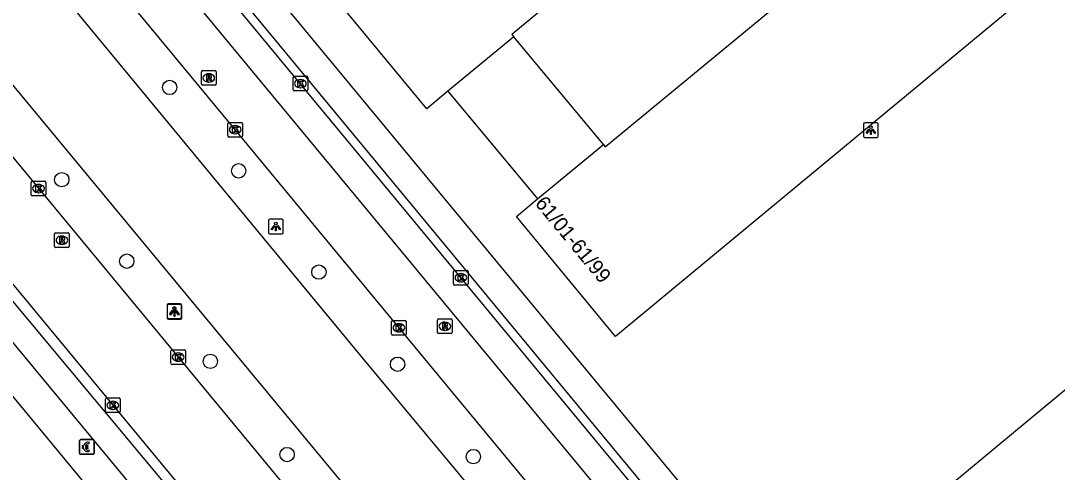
# Model space of a CAD drawing. Extents: x 159489 to 160304, y 383826 to 384530.
# Drawn here: x 159992.1 to 160062.8, y 384204.7 to 384235.5 of the extents above; entities that cross this region are included whole.
import ezdxf

# ---------------------------------------------------------------- set-up
doc = ezdxf.new("R2010")
doc.units = 0
for name, color, linetype in [('IMGEO_Betaalautomaat', 7, 'Continuous'), ('IMGEO_Boom', 7, 'Continuous'), ('IMGEO_Fietspad_gesloten', 7, 'Continuous'), ('IMGEO_Kolk', 7, 'Continuous'), ('IMGEO_Lichtpunt', 7, 'Continuous'), ('IMGEO_OVBaan_gesloten', 7, 'Continuous'), ('IMGEO_Pand', 7, 'Continuous'), ('IMGEO_Pand_nummerreeks', 7, 'Continuous'), ('IMGEO_Pand_overbouw', 7, 'Continuous'), ('IMGEO_Rijbaan_lokaal_gesloten', 7, 'Continuous'), ('IMGEO_Rioolput', 7, 'Continuous'), ('IMGEO_Voetpad_open', 7, 'Continuous')]:
    doc.layers.add(name, color=color, linetype=linetype)

msp = doc.modelspace()

# ---------------------------------------------------------------- linework, layer by layer
at = {"layer": 'IMGEO_Betaalautomaat'}
for p, q in [((159996.11, 384206.021), (159996.11, 384206.862)), ((159996.11, 384206.862), (159996.11, 384206.021)), ((159996.185, 384206.945), (159997.026, 384206.945)), ((159997.026, 384206.945), (159996.185, 384206.945)), ((159996.772, 384206.75), (159996.755, 384206.65)), ((159997.109, 384206.871), (159997.109, 384206.03)), ((159997.109, 384206.03), (159997.109, 384206.871)), ((159996.393, 384206.409), (159996.393, 384206.477)), ((159996.514, 384206.477), (159996.514, 384206.409)), ((159996.759, 384206.244), (159996.781, 384206.157)), ((159997.035, 384205.946), (159996.194, 384205.946)), ((159996.194, 384205.946), (159997.035, 384205.946))]:
    msp.add_line(p, q, dxfattribs=at)
for points in [[(159996.393, 384206.477), (159996.324, 384206.477), (159996.324, 384206.546), (159996.403, 384206.546)], [(159996.398, 384206.34), (159996.324, 384206.34), (159996.324, 384206.409), (159996.393, 384206.409)], [(159996.525, 384206.546), (159996.672, 384206.546), (159996.672, 384206.477), (159996.514, 384206.477)], [(159996.514, 384206.409), (159996.672, 384206.409), (159996.672, 384206.34), (159996.528, 384206.34)]]:
    msp.add_lwpolyline(points, dxfattribs=at)
for centre, radius, start, end in [((159996.188, 384206.868), 0.0779, 92.4484, 184.28452), ((159996.188, 384206.868), 0.0779, 92.4484, 184.28452), ((159996.686, 384206.47), 0.293, 73.01398, 165.01395), ((159997.032, 384206.868), 0.0779, 2.4484, 94.28452), ((159997.032, 384206.868), 0.0779, 2.4484, 94.28452), ((159996.188, 384206.024), 0.0779, 182.4484, 274.28452), ((159996.188, 384206.024), 0.0779, 182.4484, 274.28452), ((159996.659, 384206.395), 0.267, 191.80956, 297.03891), ((159996.692, 384206.483), 0.179, 69.32359, 159.56827), ((159996.692, 384206.41), 0.179, 202.76249, 291.86925), ((159997.032, 384206.024), 0.0779, 272.4484, 4.28452), ((159997.032, 384206.024), 0.0779, 272.4484, 4.28452)]:
    msp.add_arc(centre, radius, start, end, dxfattribs=at)
at = {"layer": 'IMGEO_Boom'}
for centre in [(160002.259, 384230.941), (159994.902, 384224.654), (160006.962, 384225.258), (159999.338, 384219.104), (160012.433, 384218.36), (160005.035, 384212.279), (160017.798, 384212.08), (160010.267, 384205.93), (160022.961, 384205.789)]:
    msp.add_circle(centre, 0.489, dxfattribs=at)
at = {"layer": 'IMGEO_Fietspad_gesloten'}
for points in [[(159957.532, 384254.825), (159960.033, 384251.817), (159960.897, 384250.561), (160029.527, 384167.731), (160030.452, 384166.645)], [(159959.452, 384254.838), (159959.937, 384254.261), (159961.686, 384252.179), (160032.453, 384167.34)]]:
    msp.add_lwpolyline(points, dxfattribs=at)
at = {"layer": 'IMGEO_Kolk'}
for p, q in [((160010.674, 384230.772), (160010.674, 384231.624)), ((160010.749, 384231.698), (160011.601, 384231.698)), ((160011.162, 384231.478), (160011.187, 384231.478)), ((160011.675, 384231.624), (160011.675, 384230.772)), ((160011.185, 384230.918), (160011.16, 384230.918)), ((160011.601, 384230.698), (160010.749, 384230.698)), ((160006.229, 384227.635), (160006.229, 384228.487)), ((160006.304, 384228.561), (160007.156, 384228.561)), ((160006.717, 384228.341), (160006.742, 384228.341)), ((160007.23, 384228.487), (160007.23, 384227.635)), ((160007.156, 384227.561), (160006.304, 384227.561)), ((160006.74, 384227.781), (160006.715, 384227.781)), ((159992.819, 384223.621), (159992.819, 384224.473)), ((159992.894, 384224.547), (159993.746, 384224.547)), ((159993.82, 384224.473), (159993.82, 384223.621)), ((159993.33, 384223.767), (159993.305, 384223.767)), ((159993.307, 384224.327), (159993.332, 384224.327)), ((159993.746, 384223.547), (159992.894, 384223.547)), ((160021.615, 384217.549), (160021.615, 384218.401)), ((160021.69, 384218.475), (160022.542, 384218.475)), ((160022.103, 384218.255), (160022.128, 384218.255)), ((160022.616, 384218.401), (160022.616, 384217.549)), ((160022.542, 384217.475), (160021.69, 384217.475)), ((160022.126, 384217.695), (160022.101, 384217.695)), ((160017.388, 384214.139), (160017.388, 384214.991)), ((160017.463, 384215.065), (160018.315, 384215.065)), ((160017.876, 384214.845), (160017.901, 384214.845)), ((160018.389, 384214.991), (160018.389, 384214.139)), ((160018.315, 384214.065), (160017.463, 384214.065)), ((160017.899, 384214.285), (160017.874, 384214.285)), ((160002.412, 384213.069), (160003.264, 384213.069)), ((160002.337, 384212.143), (160002.337, 384212.995)), ((160002.825, 384212.849), (160002.85, 384212.849)), ((160003.338, 384212.995), (160003.338, 384212.143)), ((160003.264, 384212.069), (160002.412, 384212.069)), ((160002.848, 384212.289), (160002.823, 384212.289)), ((159997.884, 384208.857), (159997.884, 384209.709)), ((159997.959, 384209.783), (159998.811, 384209.783)), ((159998.372, 384209.563), (159998.397, 384209.563)), ((159998.885, 384209.709), (159998.885, 384208.857)), ((159998.395, 384209.003), (159998.37, 384209.003)), ((159998.811, 384208.783), (159997.959, 384208.783))]:
    msp.add_line(p, q, dxfattribs=at)
for points in [[(160010.674, 384230.772), (160010.674, 384231.624)], [(160010.749, 384231.698), (160011.601, 384231.698)], [(160011.675, 384231.624), (160011.675, 384230.772)], [(160010.995, 384231.398), (160011.118, 384231.398), (160011.118, 384231.247), (160011.248, 384231.398), (160011.412, 384231.398), (160011.266, 384231.247), (160011.419, 384230.998), (160011.267, 384230.998), (160011.182, 384231.162), (160011.118, 384231.095), (160011.118, 384230.998), (160010.995, 384230.998), (160010.995, 384231.398)], [(160011.601, 384230.698), (160010.749, 384230.698)], [(160006.229, 384227.635), (160006.229, 384228.487)], [(160006.304, 384228.561), (160007.156, 384228.561)], [(160006.55, 384228.261), (160006.673, 384228.261), (160006.673, 384228.11), (160006.803, 384228.261), (160006.967, 384228.261), (160006.821, 384228.11), (160006.974, 384227.861), (160006.822, 384227.861), (160006.737, 384228.025), (160006.673, 384227.958), (160006.673, 384227.861), (160006.55, 384227.861), (160006.55, 384228.261)], [(160007.23, 384228.487), (160007.23, 384227.635)], [(160007.156, 384227.561), (160006.304, 384227.561)], [(159992.819, 384223.621), (159992.819, 384224.473)], [(159992.894, 384224.547), (159993.746, 384224.547)], [(159993.82, 384224.473), (159993.82, 384223.621)], [(159993.14, 384224.247), (159993.263, 384224.247), (159993.263, 384224.096), (159993.393, 384224.247), (159993.557, 384224.247), (159993.411, 384224.096), (159993.564, 384223.847), (159993.412, 384223.847), (159993.327, 384224.011), (159993.263, 384223.944), (159993.263, 384223.847), (159993.14, 384223.847), (159993.14, 384224.247)], [(159993.746, 384223.547), (159992.894, 384223.547)], [(160021.615, 384217.549), (160021.615, 384218.401)], [(160021.69, 384218.475), (160022.542, 384218.475)], [(160021.936, 384218.175), (160022.059, 384218.175), (160022.059, 384218.024), (160022.189, 384218.175), (160022.353, 384218.175), (160022.207, 384218.024), (160022.36, 384217.775), (160022.208, 384217.775), (160022.123, 384217.939), (160022.059, 384217.872), (160022.059, 384217.775), (160021.936, 384217.775), (160021.936, 384218.175)], [(160022.616, 384218.401), (160022.616, 384217.549)], [(160022.542, 384217.475), (160021.69, 384217.475)], [(160017.388, 384214.139), (160017.388, 384214.991)], [(160017.463, 384215.065), (160018.315, 384215.065)], [(160017.709, 384214.765), (160017.832, 384214.765), (160017.832, 384214.614), (160017.962, 384214.765), (160018.126, 384214.765), (160017.98, 384214.614), (160018.133, 384214.365), (160017.981, 384214.365), (160017.896, 384214.529), (160017.832, 384214.462), (160017.832, 384214.365), (160017.709, 384214.365), (160017.709, 384214.765)], [(160018.389, 384214.991), (160018.389, 384214.139)], [(160018.315, 384214.065), (160017.463, 384214.065)], [(160002.412, 384213.069), (160003.264, 384213.069)], [(160002.337, 384212.143), (160002.337, 384212.995)], [(160002.658, 384212.769), (160002.781, 384212.769), (160002.781, 384212.618), (160002.911, 384212.769), (160003.075, 384212.769), (160002.929, 384212.618), (160003.082, 384212.369), (160002.93, 384212.369), (160002.845, 384212.533), (160002.781, 384212.466), (160002.781, 384212.369), (160002.658, 384212.369), (160002.658, 384212.769)], [(160003.338, 384212.995), (160003.338, 384212.143)], [(160003.264, 384212.069), (160002.412, 384212.069)], [(159997.884, 384208.857), (159997.884, 384209.709)], [(159997.959, 384209.783), (159998.811, 384209.783)], [(159998.885, 384209.709), (159998.885, 384208.857)], [(159998.205, 384209.483), (159998.328, 384209.483), (159998.328, 384209.332), (159998.458, 384209.483), (159998.622, 384209.483), (159998.476, 384209.332), (159998.629, 384209.083), (159998.477, 384209.083), (159998.392, 384209.247), (159998.328, 384209.18), (159998.328, 384209.083), (159998.205, 384209.083), (159998.205, 384209.483)], [(159998.811, 384208.783), (159997.959, 384208.783)]]:
    msp.add_lwpolyline(points, dxfattribs=at)
for centre, start, end in [((160010.751, 384231.622), 91.55205, 178.44795), ((160010.751, 384231.622), 91.55205, 178.44795), ((160011.599, 384231.622), 1.55205, 88.44795), ((160011.599, 384231.622), 1.55205, 88.44795), ((160010.751, 384230.774), 181.55205, 268.44795), ((160010.751, 384230.774), 181.55205, 268.44795), ((160011.599, 384230.774), 271.55205, 358.44795), ((160011.599, 384230.774), 271.55205, 358.44795), ((160006.306, 384228.485), 91.55205, 178.44795), ((160006.306, 384228.485), 91.55205, 178.44795), ((160007.154, 384228.485), 1.55205, 88.44795), ((160007.154, 384228.485), 1.55205, 88.44795), ((160006.306, 384227.637), 181.55205, 268.44795), ((160006.306, 384227.637), 181.55205, 268.44795), ((160007.154, 384227.637), 271.55205, 358.44795), ((160007.154, 384227.637), 271.55205, 358.44795), ((159992.896, 384224.471), 91.55205, 178.44795), ((159992.896, 384224.471), 91.55205, 178.44795), ((159993.744, 384224.471), 1.55205, 88.44795), ((159993.744, 384224.471), 1.55205, 88.44795), ((159992.896, 384223.623), 181.55205, 268.44795), ((159992.896, 384223.623), 181.55205, 268.44795), ((159993.744, 384223.623), 271.55205, 358.44795), ((159993.744, 384223.623), 271.55205, 358.44795), ((160021.692, 384218.399), 91.55205, 178.44795), ((160021.692, 384218.399), 91.55205, 178.44795), ((160022.54, 384218.399), 1.55205, 88.44795), ((160022.54, 384218.399), 1.55205, 88.44795), ((160021.692, 384217.551), 181.55205, 268.44795), ((160021.692, 384217.551), 181.55205, 268.44795), ((160022.54, 384217.551), 271.55205, 358.44795), ((160022.54, 384217.551), 271.55205, 358.44795), ((160017.465, 384214.989), 91.55205, 178.44795), ((160017.465, 384214.989), 91.55205, 178.44795), ((160018.313, 384214.989), 1.55205, 88.44795), ((160018.313, 384214.989), 1.55205, 88.44795), ((160017.465, 384214.141), 181.55205, 268.44795), ((160017.465, 384214.141), 181.55205, 268.44795), ((160018.313, 384214.141), 271.55205, 358.44795), ((160018.313, 384214.141), 271.55205, 358.44795), ((160002.414, 384212.993), 91.55205, 178.44795), ((160002.414, 384212.993), 91.55205, 178.44795), ((160003.262, 384212.993), 1.55205, 88.44795), ((160003.262, 384212.993), 1.55205, 88.44795), ((160002.414, 384212.145), 181.55205, 268.44795), ((160002.414, 384212.145), 181.55205, 268.44795), ((160003.262, 384212.145), 271.55205, 358.44795), ((160003.262, 384212.145), 271.55205, 358.44795), ((159997.961, 384209.707), 91.55205, 178.44795), ((159997.961, 384209.707), 91.55205, 178.44795), ((159998.809, 384209.707), 1.55205, 88.44795), ((159998.809, 384209.707), 1.55205, 88.44795), ((159997.961, 384208.859), 181.55205, 268.44795), ((159997.961, 384208.859), 181.55205, 268.44795), ((159998.809, 384208.859), 271.55205, 358.44795), ((159998.809, 384208.859), 271.55205, 358.44795)]:
    msp.add_arc(centre, 0.0765, start, end, dxfattribs=at)
for centre, major_axis, ratio, start_param, end_param in [((160011.161, 384231.198), (-0.387, 0.002), 0.722429, 4.712389, 7.853982), ((160011.186, 384231.198), (-0.39, 0.002), 0.717154, 1.570796, 4.712389), ((160006.716, 384228.061), (-0.387, 0.002), 0.722429, 4.712389, 7.853982), ((160006.741, 384228.061), (-0.39, 0.002), 0.717154, 1.570796, 4.712389), ((159993.306, 384224.047), (-0.387, 0.002), 0.722429, 4.712389, 7.853982), ((159993.331, 384224.047), (-0.39, 0.002), 0.717154, 1.570796, 4.712389), ((160022.102, 384217.975), (-0.387, 0.002), 0.722429, 4.712389, 7.853982), ((160022.127, 384217.975), (-0.39, 0.002), 0.717154, 1.570796, 4.712389), ((160017.875, 384214.565), (-0.387, 0.002), 0.722429, 4.712389, 7.853982), ((160017.9, 384214.565), (-0.39, 0.002), 0.717154, 1.570796, 4.712389), ((160002.824, 384212.569), (-0.387, 0.002), 0.722429, 4.712389, 7.853982), ((160002.849, 384212.569), (-0.39, 0.002), 0.717154, 1.570796, 4.712389), ((159998.371, 384209.283), (-0.387, 0.002), 0.722429, 4.712389, 7.853982), ((159998.396, 384209.283), (-0.39, 0.002), 0.717154, 1.570796, 4.712389)]:
    msp.add_ellipse(centre, major_axis=major_axis, ratio=ratio, start_param=start_param, end_param=end_param, dxfattribs=at)
at = {"layer": 'IMGEO_Lichtpunt'}
for p, q in [((160049.567, 384228.437), (160049.567, 384227.63)), ((160049.567, 384228.437), (160049.567, 384227.63)), ((160050.469, 384228.532), (160049.661, 384228.532)), ((160050.469, 384228.532), (160049.661, 384228.532)), ((160050.563, 384227.63), (160050.563, 384228.437)), ((160050.563, 384227.63), (160050.563, 384228.437)), ((160049.661, 384227.536), (160050.469, 384227.536)), ((160049.661, 384227.536), (160050.469, 384227.536)), ((160009.002, 384221.871), (160009.002, 384221.064)), ((160009.002, 384221.871), (160009.002, 384221.064)), ((160009.904, 384221.966), (160009.096, 384221.966)), ((160009.904, 384221.966), (160009.096, 384221.966)), ((160009.998, 384221.064), (160009.998, 384221.871)), ((160009.998, 384221.064), (160009.998, 384221.871)), ((160009.096, 384220.97), (160009.904, 384220.97)), ((160009.096, 384220.97), (160009.904, 384220.97)), ((160002.08, 384216.108), (160002.08, 384215.301)), ((160002.08, 384216.108), (160002.08, 384215.301)), ((160002.089, 384216.049), (160002.089, 384215.242)), ((160002.089, 384216.049), (160002.089, 384215.242)), ((160002.982, 384216.203), (160002.174, 384216.203)), ((160002.982, 384216.203), (160002.174, 384216.203)), ((160002.991, 384216.144), (160002.183, 384216.144)), ((160002.991, 384216.144), (160002.183, 384216.144)), ((160003.076, 384215.301), (160003.076, 384216.108)), ((160003.076, 384215.301), (160003.076, 384216.108)), ((160003.085, 384215.242), (160003.085, 384216.049)), ((160003.085, 384215.242), (160003.085, 384216.049)), ((160002.174, 384215.207), (160002.982, 384215.207)), ((160002.174, 384215.207), (160002.982, 384215.207)), ((160002.183, 384215.148), (160002.991, 384215.148)), ((160002.183, 384215.148), (160002.991, 384215.148))]:
    msp.add_line(p, q, dxfattribs=at)
for points in [[(160049.941, 384228.101), (160049.98, 384228.073), (160049.792, 384227.811), (160049.754, 384227.838), (160049.941, 384228.101)], [(160050.043, 384228.053), (160050.09, 384228.053), (160050.09, 384227.731), (160050.043, 384227.731), (160050.043, 384228.053)], [(160050.153, 384228.073), (160050.191, 384228.1), (160050.378, 384227.838), (160050.339, 384227.81), (160050.153, 384228.073)], [(160009.376, 384221.535), (160009.415, 384221.507), (160009.227, 384221.245), (160009.189, 384221.272), (160009.376, 384221.535)], [(160009.588, 384221.507), (160009.626, 384221.534), (160009.813, 384221.272), (160009.774, 384221.244), (160009.588, 384221.507)], [(160009.478, 384221.487), (160009.525, 384221.487), (160009.525, 384221.165), (160009.478, 384221.165), (160009.478, 384221.487)], [(160002.454, 384215.772), (160002.493, 384215.744), (160002.305, 384215.482), (160002.267, 384215.509), (160002.454, 384215.772)], [(160002.463, 384215.713), (160002.502, 384215.685), (160002.314, 384215.423), (160002.276, 384215.45), (160002.463, 384215.713)], [(160002.556, 384215.724), (160002.603, 384215.724), (160002.603, 384215.402), (160002.556, 384215.402), (160002.556, 384215.724)], [(160002.565, 384215.665), (160002.612, 384215.665), (160002.612, 384215.343), (160002.565, 384215.343), (160002.565, 384215.665)], [(160002.666, 384215.744), (160002.704, 384215.771), (160002.891, 384215.509), (160002.852, 384215.481), (160002.666, 384215.744)], [(160002.675, 384215.685), (160002.713, 384215.712), (160002.9, 384215.45), (160002.861, 384215.422), (160002.675, 384215.685)]]:
    msp.add_lwpolyline(points, dxfattribs=at)
for centre in [(160050.066, 384228.235), (160009.501, 384221.669), (160002.579, 384215.906), (160002.588, 384215.847)]:
    msp.add_circle(centre, 0.0994, dxfattribs=at)
for centre, start, end in [((160049.661, 384228.437), 90, 180), ((160049.661, 384228.437), 90, 180), ((160050.469, 384228.437), 0, 90), ((160050.469, 384228.437), 0, 90), ((160049.661, 384227.63), 180, 270), ((160049.661, 384227.63), 180, 270), ((160050.469, 384227.63), 270, 0), ((160050.469, 384227.63), 270, 360), ((160009.096, 384221.871), 90, 180), ((160009.096, 384221.871), 90, 180), ((160009.904, 384221.871), 0, 90), ((160009.904, 384221.871), 0, 90), ((160009.096, 384221.064), 180, 270), ((160009.096, 384221.064), 180, 270), ((160009.904, 384221.064), 270, 0), ((160009.904, 384221.064), 270, 360), ((160002.174, 384216.108), 90, 180), ((160002.174, 384216.108), 90, 180), ((160002.183, 384216.049), 90, 180), ((160002.183, 384216.049), 90, 180), ((160002.982, 384216.108), 0, 90), ((160002.982, 384216.108), 0, 90), ((160002.991, 384216.049), 0, 90), ((160002.991, 384216.049), 0, 90), ((160002.174, 384215.301), 180, 270), ((160002.174, 384215.301), 180, 270), ((160002.183, 384215.242), 180, 270), ((160002.183, 384215.242), 180, 270), ((160002.982, 384215.301), 270, 0), ((160002.982, 384215.301), 270, 360), ((160002.991, 384215.242), 270, 0), ((160002.991, 384215.242), 270, 360)]:
    msp.add_arc(centre, 0.0946, start, end, dxfattribs=at)
at = {"layer": 'IMGEO_OVBaan_gesloten'}
for points in [[(160035.565, 384188.31), (160015.314, 384212.637), (159985.373, 384248.854), (159983.467, 384251.216)], [(159981.084, 384243.71), (160030.552, 384184.07)]]:
    msp.add_lwpolyline(points, dxfattribs=at)
at = {"layer": 'IMGEO_Pand'}
for points in [[(160050.593, 384268.799), (160059.329, 384258.248), (160056.671, 384256.048), (160058.984, 384253.255), (160061.641, 384255.455), (160070.224, 384245.089), (160032.647, 384213.964), (160025.898, 384222.145), (160027.349, 384223.341), (160031.839, 384227.045), (160031.963, 384226.894), (160060.808, 384250.684), (160054.416, 384258.366), (160025.596, 384234.545), (160025.72, 384234.395), (160021.234, 384230.687), (160019.785, 384229.489), (160013.014, 384237.682), (160018.664, 384242.36)], [(160066.866, 384173.044), (160047.105, 384196.925), (160084.614, 384228.014), (160091.579, 384219.62), (160089.274, 384217.715), (160090.807, 384215.868), (160092.942, 384217.633), (160095.794, 384214.204), (160093.659, 384212.439), (160095.188, 384210.589), (160097.49, 384212.496), (160097.572, 384212.398), (160104.42, 384204.111), (160104.352, 384204.054)]]:
    msp.add_lwpolyline(points, dxfattribs=at)
at = {"layer": 'IMGEO_Pand_overbouw'}
msp.add_lwpolyline([(160025.72, 384234.395), (160021.234, 384230.687), (160027.349, 384223.341), (160031.839, 384227.045)], close=True, dxfattribs=at)
at = {"layer": 'IMGEO_Rijbaan_lokaal_gesloten'}
for points in [[(159964.53, 384278.991), (160037.958, 384190.34)], [(160030.037, 384171.103), (159961.57, 384253.773), (159960.762, 384254.768)], [(160028.141, 384182.05), (159969.786, 384252.506)], [(159994.505, 384251.312), (159992.986, 384250.055), (160033.227, 384201.454), (160037.343, 384196.516), (160038.858, 384197.779)]]:
    msp.add_lwpolyline(points, dxfattribs=at)
at = {"layer": 'IMGEO_Rioolput'}
for p, q in [((160004.426, 384231.16), (160004.426, 384232.012)), ((160004.501, 384232.086), (160005.353, 384232.086)), ((160004.914, 384231.866), (160004.939, 384231.866)), ((160005.427, 384232.012), (160005.427, 384231.16)), ((160005.353, 384231.086), (160004.501, 384231.086)), ((160004.937, 384231.306), (160004.912, 384231.306)), ((159994.412, 384220.104), (159994.412, 384220.956)), ((159994.487, 384221.03), (159995.339, 384221.03)), ((159995.413, 384220.956), (159995.413, 384220.104)), ((159994.923, 384220.25), (159994.898, 384220.25)), ((159994.9, 384220.81), (159994.925, 384220.81)), ((159995.339, 384220.03), (159994.487, 384220.03)), ((160020.594, 384215.166), (160021.446, 384215.166)), ((160020.519, 384214.24), (160020.519, 384215.092)), ((160021.007, 384214.946), (160021.032, 384214.946)), ((160021.52, 384215.092), (160021.52, 384214.24)), ((160021.446, 384214.166), (160020.594, 384214.166)), ((160021.03, 384214.386), (160021.005, 384214.386))]:
    msp.add_line(p, q, dxfattribs=at)
for points in [[(160004.426, 384231.16), (160004.426, 384232.012)], [(160004.501, 384232.086), (160005.353, 384232.086)], [(160005.015, 384231.784), (160004.763, 384231.786), (160004.763, 384231.386)], [(160004.763, 384231.386), (160004.887, 384231.386), (160004.887, 384231.548), (160004.898, 384231.548)], [(160004.941, 384231.705), (160004.887, 384231.705), (160004.887, 384231.624)], [(160004.887, 384231.624), (160004.939, 384231.624)], [(160004.945, 384231.519), (160005.016, 384231.386), (160005.156, 384231.386), (160005.091, 384231.512)], [(160005.427, 384232.012), (160005.427, 384231.16)], [(160005.353, 384231.086), (160004.501, 384231.086)], [(159994.412, 384220.104), (159994.412, 384220.956)], [(159994.487, 384221.03), (159995.339, 384221.03)], [(159995.413, 384220.956), (159995.413, 384220.104)], [(159995.001, 384220.728), (159994.749, 384220.73), (159994.749, 384220.33)], [(159994.749, 384220.33), (159994.873, 384220.33), (159994.873, 384220.492), (159994.884, 384220.492)], [(159994.927, 384220.649), (159994.873, 384220.649), (159994.873, 384220.568)], [(159994.873, 384220.568), (159994.925, 384220.568)], [(159994.931, 384220.463), (159995.002, 384220.33), (159995.142, 384220.33), (159995.077, 384220.456)], [(159995.339, 384220.03), (159994.487, 384220.03)], [(160020.594, 384215.166), (160021.446, 384215.166)], [(160020.519, 384214.24), (160020.519, 384215.092)], [(160021.108, 384214.864), (160020.856, 384214.866), (160020.856, 384214.466)], [(160020.856, 384214.466), (160020.98, 384214.466), (160020.98, 384214.628), (160020.991, 384214.628)], [(160021.034, 384214.785), (160020.98, 384214.785), (160020.98, 384214.704)], [(160020.98, 384214.704), (160021.032, 384214.704)], [(160021.038, 384214.599), (160021.109, 384214.466), (160021.249, 384214.466), (160021.184, 384214.592)], [(160021.52, 384215.092), (160021.52, 384214.24)], [(160021.446, 384214.166), (160020.594, 384214.166)]]:
    msp.add_lwpolyline(points, dxfattribs=at)
for centre, radius, start, end in [((160004.503, 384232.01), 0.0765, 91.55205, 178.44795), ((160004.503, 384232.01), 0.0765, 91.55205, 178.44795), ((160004.897, 384231.495), 0.0533, 26.02933, 88.69889), ((160004.923, 384231.813), 0.19, 274.7715, 282.96867), ((160004.947, 384231.609), 0.0964, 77.00612, 93.18647), ((160004.961, 384231.666), 0.0378, 276.66336, 79.67722), ((160005.014, 384231.674), 0.109, 350.36119, 89.41601), ((160005.012, 384231.674), 0.112, 277.58423, 350.98172), ((160004.996, 384231.459), 0.108, 29.51342, 73.79051), ((160005.351, 384232.01), 0.0765, 1.55205, 88.44795), ((160005.351, 384232.01), 0.0765, 1.55205, 88.44795), ((160004.503, 384231.162), 0.0765, 181.55205, 268.44795), ((160004.503, 384231.162), 0.0765, 181.55205, 268.44795), ((160005.351, 384231.162), 0.0765, 271.55205, 358.44795), ((160005.351, 384231.162), 0.0765, 271.55205, 358.44795), ((159994.489, 384220.954), 0.0765, 91.55205, 178.44795), ((159994.489, 384220.954), 0.0765, 91.55205, 178.44795), ((159995.337, 384220.954), 0.0765, 1.55205, 88.44795), ((159995.337, 384220.954), 0.0765, 1.55205, 88.44795), ((159994.489, 384220.106), 0.0765, 181.55205, 268.44795), ((159994.489, 384220.106), 0.0765, 181.55205, 268.44795), ((159994.883, 384220.439), 0.0533, 26.02933, 88.69889), ((159994.909, 384220.757), 0.19, 274.7715, 282.96867), ((159994.933, 384220.553), 0.0964, 77.00612, 93.18647), ((159994.947, 384220.61), 0.0378, 276.66336, 79.67722), ((159995, 384220.618), 0.109, 350.36119, 89.41601), ((159994.998, 384220.618), 0.112, 277.58423, 350.98172), ((159994.982, 384220.403), 0.108, 29.51342, 73.79051), ((159995.337, 384220.106), 0.0765, 271.55205, 358.44795), ((159995.337, 384220.106), 0.0765, 271.55205, 358.44795), ((160020.596, 384215.09), 0.0765, 91.55205, 178.44795), ((160020.596, 384215.09), 0.0765, 91.55205, 178.44795), ((160021.444, 384215.09), 0.0765, 1.55205, 88.44795), ((160021.444, 384215.09), 0.0765, 1.55205, 88.44795), ((160020.99, 384214.575), 0.0533, 26.02933, 88.69889), ((160021.016, 384214.893), 0.19, 274.7715, 282.96867), ((160021.04, 384214.689), 0.0964, 77.00612, 93.18647), ((160021.054, 384214.746), 0.0378, 276.66336, 79.67722), ((160021.107, 384214.754), 0.109, 350.36119, 89.41601), ((160021.105, 384214.754), 0.112, 277.58423, 350.98172), ((160021.089, 384214.539), 0.108, 29.51342, 73.79051), ((160020.596, 384214.242), 0.0765, 181.55205, 268.44795), ((160020.596, 384214.242), 0.0765, 181.55205, 268.44795), ((160021.444, 384214.242), 0.0765, 271.55205, 358.44795), ((160021.444, 384214.242), 0.0765, 271.55205, 358.44795)]:
    msp.add_arc(centre, radius, start, end, dxfattribs=at)
for centre, major_axis, ratio, start_param, end_param in [((160004.913, 384231.586), (-0.387, 0.002), 0.722429, 4.712389, 7.853982), ((160004.938, 384231.586), (-0.39, 0.002), 0.717154, 1.570796, 4.712389), ((159994.899, 384220.53), (-0.387, 0.002), 0.722429, 4.712389, 7.853982), ((159994.924, 384220.53), (-0.39, 0.002), 0.717154, 1.570796, 4.712389), ((160021.006, 384214.666), (-0.387, 0.002), 0.722429, 4.712389, 7.853982), ((160021.031, 384214.666), (-0.39, 0.002), 0.717154, 1.570796, 4.712389)]:
    msp.add_ellipse(centre, major_axis=major_axis, ratio=ratio, start_param=start_param, end_param=end_param, dxfattribs=at)
at = {"layer": 'IMGEO_Voetpad_open'}
for points in [[(159937.427, 384324.203), (159935.905, 384322.929), (160048.804, 384186.671)], [(160050.34, 384187.958), (160045.884, 384193.335), (160045.088, 384194.296), (160035.789, 384205.516), (160035.01, 384206.456), (159975.49, 384278.275)], [(159994.505, 384251.312), (160034.744, 384202.714), (160038.858, 384197.779)], [(159967.686, 384229.02), (159982.197, 384221.174), (160029.234, 384164.348)]]:
    msp.add_lwpolyline(points, dxfattribs=at)

# ---------------------------------------------------------------- texts
at = {"layer": 'IMGEO_Pand_nummerreeks'}
msp.add_text('61/01-61/99', height=1, rotation=309.52242, dxfattribs=at).set_placement((160027.12, 384223.02))

doc.saveas('drawing.dxf')
